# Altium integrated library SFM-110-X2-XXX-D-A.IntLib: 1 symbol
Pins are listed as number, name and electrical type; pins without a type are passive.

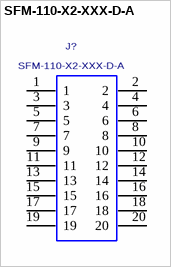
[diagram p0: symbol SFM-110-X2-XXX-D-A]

## SFM-110-X2-XXX-D-A
designator J?
SOCKET STRIP, .050" (1.27mm) PITCH, SURFACE MOUNT.; MANUFACTURER: SAMTEC
footprint SFM-110-X2-XXX-D-A
pins: 1, 2, 3, 4, 5, 6, 7, 8, 9, 10, 11, 12, 13, 14, 15, 16, 17, 18, 19, 20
